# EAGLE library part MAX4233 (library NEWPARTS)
High-Output-Drive, 10MHz, 10V/us, Rail-to_rail I/O Op Amps with Shutdown in SC70
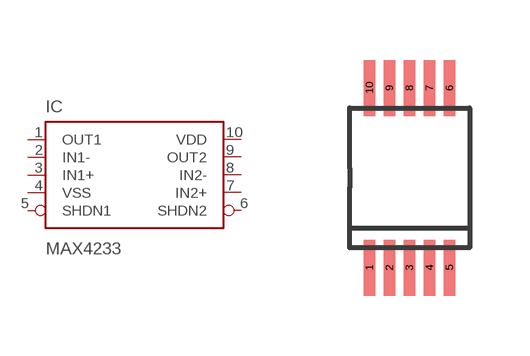
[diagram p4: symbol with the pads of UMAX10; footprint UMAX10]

Designator prefix IC

## MAX4233  [UMAX10]
1  OUT1  in
2  IN1-  in
3  IN1+  pas
4  VSS  pwr
5  SHDN1  in
6  SHDN2  out
7  IN2+  in
8  IN2-  in
9  OUT2  out
10  VDD  pas

## Footprint UMAX10 (pad centres in mm)
micro MAX Package
smd 0.28 x 1.4: 1 -1,-2; 2 -0.5,-2; 3 0,-2; 4 0.5,-2; 5 1,-2; 6 1,2.5; 7 0.5,2.5; 8 0,2.5; 9 -0.5,2.5; 10 -1,2.5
